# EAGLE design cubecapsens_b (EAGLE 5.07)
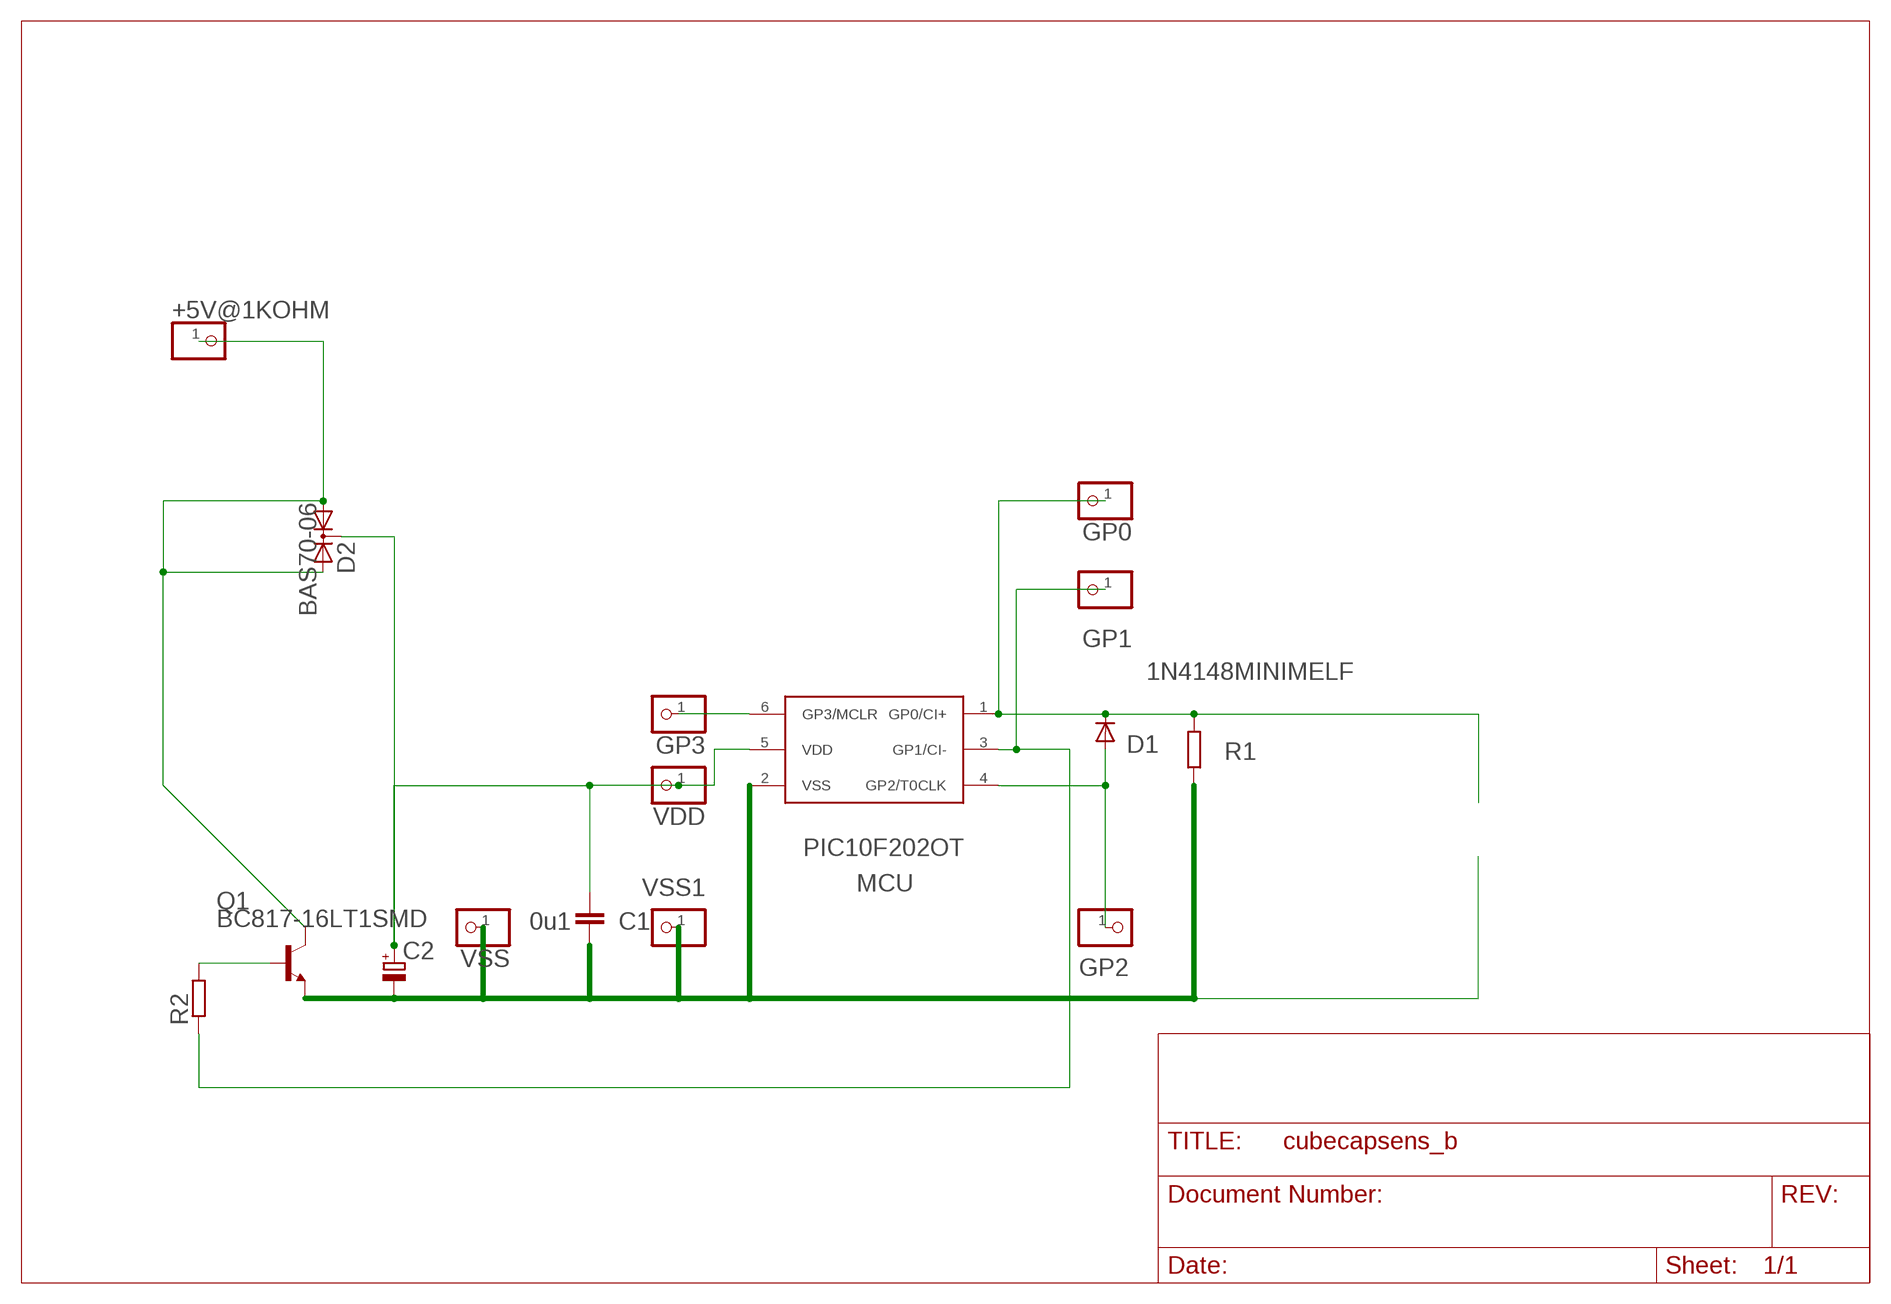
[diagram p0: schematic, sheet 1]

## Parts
+5V@1KOHM  PINHD-1X1INCH  [1X01]
C1  0u1  C-EUC1206  [C1206]
C2  CPOL-EUF  [PANASONIC_F]
D1  1N4148MINIMELF  [MINIMELF]
D2  BAS70-06  [SOT23]
GP0  PINHD-1X1INCH  [1X01]
GP1  PINHD-1X1INCH  [1X01]
GP2  PINHD-1X1INCH  [1X01]
GP3  PINHD-1X1INCH  [1X01]
MCU  PIC10F202OT  [SOT23-6]
Q1  BC817-16LT1SMD  [SOT23-BEC]
R1  R-EU_R1206  [R1206]
R2  R-EU_R1206  [R1206]
VDD  PINHD-1X1INCH  [1X01]
VSS  PINHD-1X1INCH  [1X01]
VSS1  PINHD-1X1INCH  [1X01]

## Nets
GP0: D1.C GP0.1 MCU.1(GP0/CI+) R1.2
GP1: GP1.1 MCU.3(GP1/CI-) R2.1
GP2: D1.A GP2.1 MCU.4(GP2/T0CLK)
GP3: GP3.1 MCU.6(GP3/MCLR)
N$1: +5V@1KOHM.1 D2.1(A1) D2.2(A2) Q1.C
N$4: Q1.B R2.2
VDD1: C1.2 C2.+ D2.3(C) MCU.5(VDD) VDD.1
VSS1: C1.1 C2.- MCU.2(VSS) Q1.E R1.1 VSS1.1 VSS.1

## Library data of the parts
+5V@1KOHM GP0 GP1-GP3 VDD VSS VSS1 = pinhead(2):PINHD-1X1: PIN HEADER
C1 = rcl:C-EU: CAPACITOR, European symbol
C2 = rcl-2:CPOL-EU: POLARIZED CAPACITOR, European symbol
D1 = diode-1:1N4148: DIODE
D2 = diode-1:BAS70-06: Silicon Schottky Diodes General-purpose diode for high-speed switching
MCU = microchip-3:PIC10F2*: uPC nW 0,25/0,5k Program Flash memory Comparator
Q1 = transistor-npn:BC817*: NPN Transistor
R1 R2 = rcl-2:R-EU_: RESISTOR, European symbol

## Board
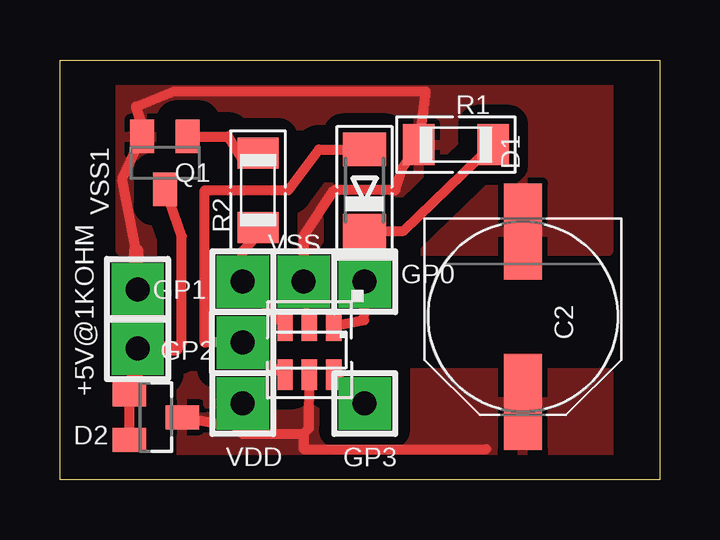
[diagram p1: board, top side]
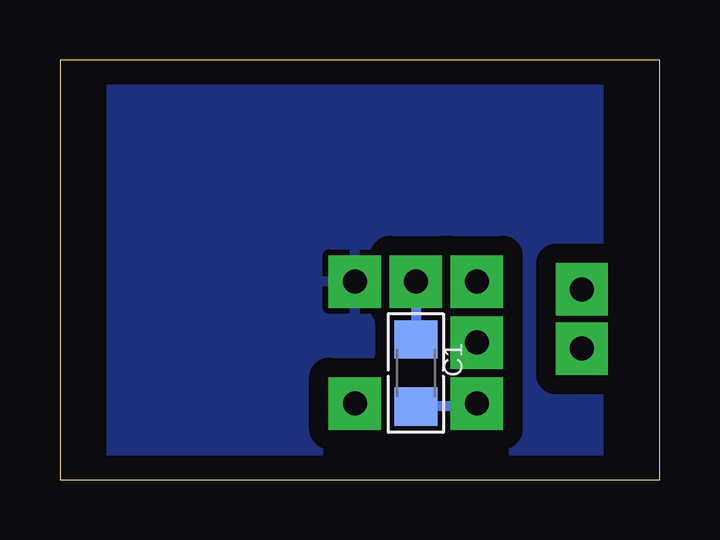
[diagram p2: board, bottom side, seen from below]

Size 25 x 17.5 mm. Coordinates in mm from the lower left corner, seen from the top.
Outline: 0,0 0,17.5 25,17.5 25,0 0,0
Copper layers (1*16): Top 0.035mm / dielectric 1.5mm / Bottom 0.035mm
Design rules "default": minimum track width 10mil, minimum drill 24mil, track to track 8mil, track to pad 8mil, pad to pad 8mil, via to via 8mil, smd to smd 8mil, copper to edge 40mil, drill to drill 8mil, minimum pad ring 10mil, minimum via ring 8mil, stop-mask expansion 4mil, vias tented up to drill 0mil, thermal gap 10mil

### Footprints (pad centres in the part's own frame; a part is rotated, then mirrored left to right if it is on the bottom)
1X01 = drill 1 pad 2.184 square: 1 0,0
C1206 = smd 1.6 x 1.8: 1 -1.4,0; 2 1.4,0
PANASONIC_F = smd 4 x 1.6: + 3.55,0; - -3.55,0
MINIMELF = smd 1.4 x 1.8: A 1.7,0; C -1.7,0
SOT23 = smd 1 x 1.4: 1 -0.95,-1.1; 2 0.95,-1.1; 3 0,1.1
SOT23-6 = smd 0.635 x 1.27: 1 -1.016,-1.016; 2 0,-1.016; 3 1.016,-1.016; 4 1.016,1.016; 5 0,1.016; 6 -1.016,1.016
SOT23-BEC = smd 1 x 1.4: B -0.95,-1.1; C 0,1.1; E 0.95,-1.1
R1206 = smd 1.3 x 1.7: 1 -1.55,0; 2 1.55,0

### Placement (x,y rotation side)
+5V@1KOHM  3.24,5.46 90 top
C1  10.16,4.45 270 bottom
C2  19.3,6.79 270 top
D1  12.7,12.06 90 top
D2  4,2.6 270 top
GP0  12.7,8.26 0 top
GP1  7.62,8.26 0 top
GP2  7.62,5.71 90 top
GP3  12.7,3.17 0 top
MCU  10.4,5.4 180 top
Q1  4.38,13.21 180 top
R1  16.51,13.97 0 top
R2  8.26,12.06 90 top
VDD  7.62,3.17 0 top
VSS  10.16,8.26 0 top
VSS1  3.24,7.94 90 top

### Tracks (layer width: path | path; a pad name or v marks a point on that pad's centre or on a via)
GP0
  Top 0.406: MCU.1 12.68,6.65 12.7,6.99 GP0.1 D1.C 14.33,10.37 R1.2
  pour Bottom (isolate 0.813): 2.54,17.14 22.86,17.14 22.86,-0.64 2.54,-0.64
GP1
  Top 0.406: MCU.3 GP1.1 7.62,9.53 8.74,10.64 R2.1
GP2
  Top 0.406: MCU.4 8.4,4.93 GP2.1 6.03,5.71 6.03,12.06 9.53,12.06 10.79,13.77 D1.A
GP3
  Top 0.406: MCU.6 GP3.1
N$1
  Top 0.406: 4.83,5.46 5.08,5.71 5.08,10.14 Q1.C | 2.86,3.57 3.24,3.57 D2.1 D2.2 | 2.86,3.57 2.86,3.49 | 2.86,3.57 2.86,3.81 | 3.17,5.46 +5V@1KOHM.1
  Top 0.61: +5V@1KOHM.1 4.83,5.46 | 2.86,3.81 3.17,4.45 3.17,5.46
N$4
  Top 0.406: Q1.B 7,14.31 7.62,13.34 8.74,13.34 R2.2
VDD1
  Top 0.406: D2.3 6.73,2.29 6.99,2.54 | 6.99,2.54 VDD.1 | MCU.5 10.38,2.13 10.16,1.91 | 10.16,1.91 7.62,1.91 6.99,2.54 | 19.12,1.97 C2.+ | 17.78,1.27 10.16,1.27 10.16,1.91
  Bottom 0.406: C1.2 7.75,3.04 VDD.1
  pour Top (isolate 0.813): 5.08,4.45 22.86,4.45 22.86,-0.64 5.08,-0.64
VSS1
  Top 0.254: MCU.2 10.16,7.62 VSS.1
  Top 0.406: VSS1.1 3.17,7.94 | 3.17,9.53 2.6,12.53 Q1.E 3.49,14.56 3.17,15.56 4.76,16.19 15.24,16.19 R1.1 14.29,13.02 13.97,12.06 11.43,12.06 10.16,10.16 VSS.1
  Top 0.61: 3.17,7.94 3.17,9.53
  Bottom 0.406: VSS.1 C1.1
  pour Top (isolate 0.813): 2.54,9.53 2.54,16.51 22.86,16.51 22.86,9.53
